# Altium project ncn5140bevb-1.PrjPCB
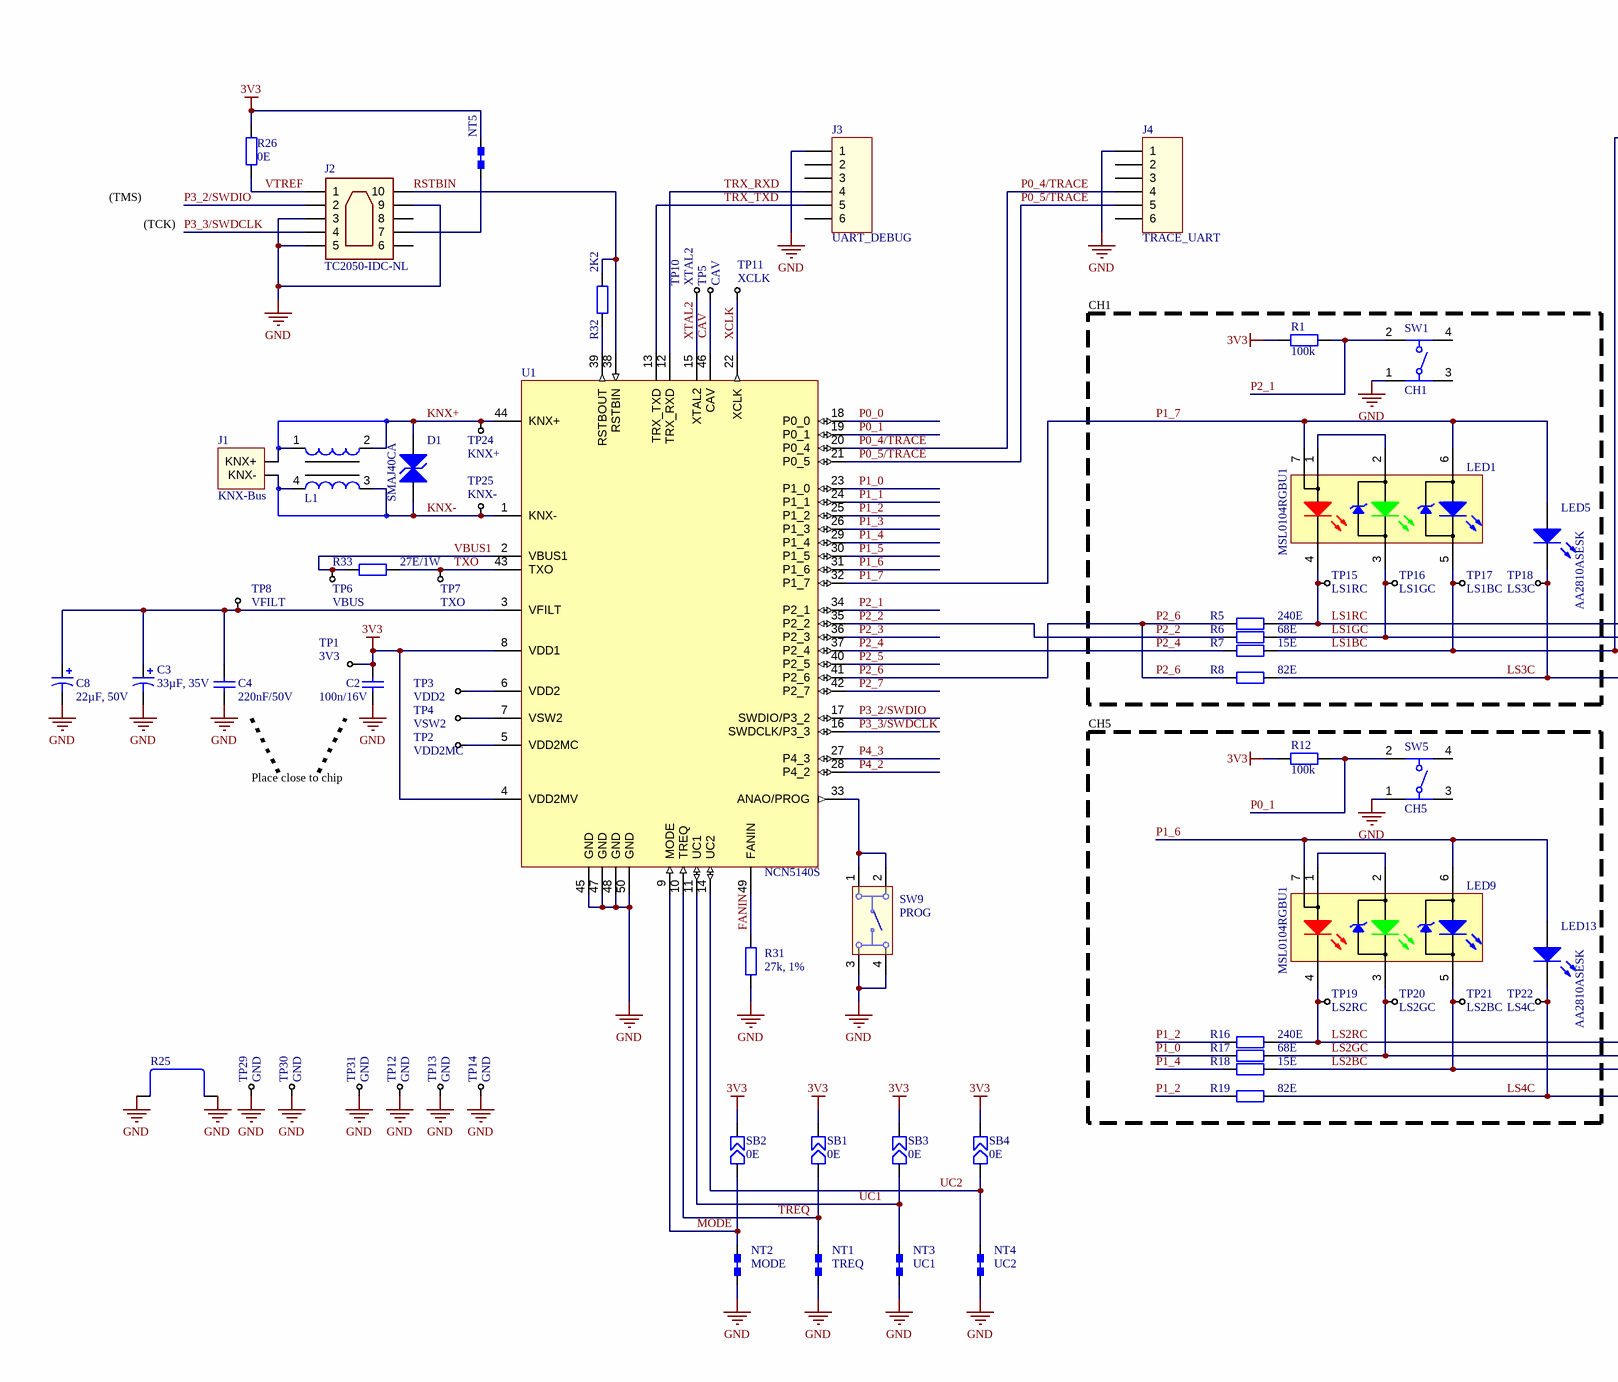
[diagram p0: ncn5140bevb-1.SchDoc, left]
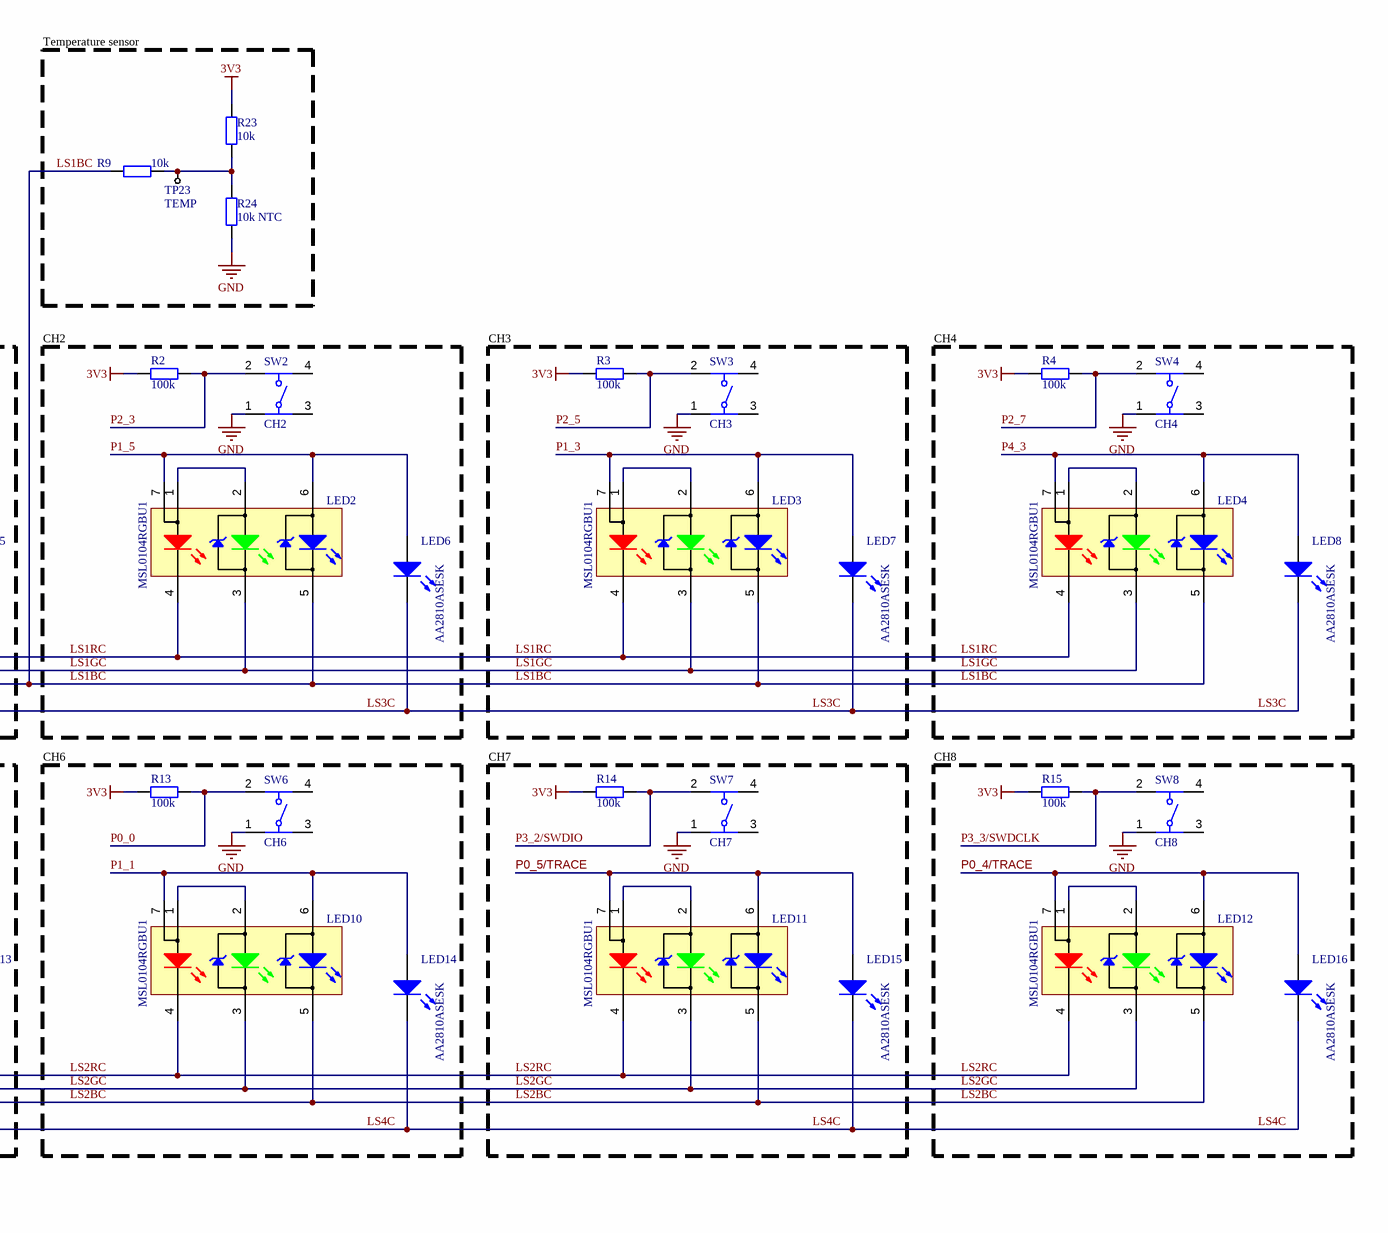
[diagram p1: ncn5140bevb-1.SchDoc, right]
ProjectBoardName: ncn5140bevb-1; ProjectEngineer: Tijl Schepens; ProjectOrganization: ON Semiconductor — Energy Management Products; ProjectRevision: -; ProjectTitle: NCN5140 EVB with tactile buttons
1 sheet, 96 parts. Net scope: global (net labels, ports and power ports of the same name join across sheets).
Board file: ncn5140bevb-1.PcbDoc

## Sheet ncn5140bevb-1.SchDoc
size A2; Engineer: Tijl Schepens; Organization: ON Semiconductor — Energy Management Products; Revision: -; SheetNumber: 1; SheetTotal: 1; BoardName: ncn5140bevb-1

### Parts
C2  value 100n/16V  [CAPC1608L]  (hidden comment: Cap)
C3  value 33µF, 35V  [T598]  (hidden comment: T598D336M035ATE065)
C4  value 220nF/50V  [CAPC1608L]  (hidden comment: Cap)
C8  value 22µF, 50V  [CAPPSMD-6.3x5.8_L]  (hidden comment: Cap)
D1  SMAJ40CA  [DIOM4326X23N]
J1  KNX-Bus  [EIB_BUS_COUPLER_2P_FULL_8.5]
J2  TC2050-IDC-NL  [TC2050-IDC-NL]
J3  Usage: UART_DEBUG  [61300611121]  (hidden comment: 61300611121)
J4  Usage: TRACE_UART  [61300611121]  (hidden comment: 61300611121)
L1  50475C  [5000_Series]  (value not drawn)  (net tie, no BOM)
LED1  MSL0104RGBU1  [MSL0104RGB]
LED2  MSL0104RGBU1  [MSL0104RGB]
LED3  MSL0104RGBU1  [MSL0104RGB]
LED4  MSL0104RGBU1  [MSL0104RGB]
LED5  AA2810ASESK  [AA2810A]
LED6  AA2810ASESK  [AA2810A]
LED7  AA2810ASESK  [AA2810A]
LED8  AA2810ASESK  [AA2810A]
LED9  MSL0104RGBU1  [MSL0104RGB]
LED10  MSL0104RGBU1  [MSL0104RGB]
LED11  MSL0104RGBU1  [MSL0104RGB]
LED12  MSL0104RGBU1  [MSL0104RGB]
LED13  AA2810ASESK  [AA2810A]
LED14  AA2810ASESK  [AA2810A]
LED15  AA2810ASESK  [AA2810A]
LED16  AA2810ASESK  [AA2810A]
NT1  TREQ  [NetTie-1005L]  (net tie, no BOM)
NT2  MODE  [NetTie-1005L]  (net tie, no BOM)
NT3  UC1  [NetTie-1005L]  (net tie, no BOM)
NT4  UC2  [NetTie-1005L]  (net tie, no BOM)
NT5  NetTie  [NetTie-1608L]  (value not drawn)  (net tie, no BOM)
R1  value 100k  [RESC1608L]
R2  value 100k  [RESC1608L]
R3  value 100k  [RESC1608L]
R4  value 100k  [RESC1608L]
R5  value 240E  [RESC1608L]
R6  value 68E  [RESC1608L]
R7  value 15E  [RESC1608L]
R8  value 82E  [RESC1608L]
R9  value 10k  [RESC1608L]
R12  value 100k  [RESC1608L]
R13  value 100k  [RESC1608L]
R14  value 100k  [RESC1608L]
R15  value 100k  [RESC1608L]
R16  value 240E  [RESC1608L]
R17  value 68E  [RESC1608L]
R18  value 15E  [RESC1608L]
R19  value 82E  [RESC1608L]
R23  value 10k  [RESC1608L]
R24  value 10k NTC  [RESC1608L]
R25  D3082-05  [Groundbar D3082-05]  (value not drawn)
R26  value 0E  [RESC1608L]
R31  value 27k, 1%  [RESC1608L]
R32  value 2K2  [RESC1608L]
R33  value 27E/1W  [RESC6332N]
SB1  value 0E  [1005-SB]  (hidden comment: TREQ)
SB2  value 0E  [1005-SB]  (hidden comment: MODE)
SB3  value 0E  [1005-SB]  (hidden comment: UC1)
SB4  value 0E  [1005-SB]  (hidden comment: UC2)
SW1  CH1  [430182070816]
SW2  CH2  [430182070816]
SW3  CH3  [430182070816]
SW4  CH4  [430182070816]
SW5  CH5  [430182070816]
SW6  CH6  [430182070816]
SW7  CH7  [430182070816]
SW8  CH8  [430182070816]
SW9  PROG  [430181038816]
TP1  3V3  [testpointpg-th]  (no BOM)
TP2  VDD2MC  [testpointpg-smt_N]  (no BOM)
TP3  VDD2  [testpointpg-smt_N]  (no BOM)
TP4  VSW2  [testpointpg-smt_N]  (no BOM)
TP5  CAV  [testpointpg-smt]  (no BOM)
TP6  VBUS  [testpointpg-th]  (no BOM)
TP7  TXO  [testpointpg-th]  (no BOM)
TP8  VFILT  [testpointpg-th]  (no BOM)
TP10  XTAL2  [testpointpg-smt_N]  (no BOM)
TP11  XCLK  [testpointpg-th]  (no BOM)
TP12  GND  [testpointpg-th]  (no BOM)
TP13  GND  [testpointpg-th]  (no BOM)
TP14  GND  [testpointpg-th]  (no BOM)
TP15  LS1RC  [testpointpg-th]  (no BOM)
TP16  LS1GC  [testpointpg-th]  (no BOM)
TP17  LS1BC  [testpointpg-th]  (no BOM)
TP18  LS3C  [testpointpg-th]  (no BOM)
TP19  LS2RC  [testpointpg-th]  (no BOM)
TP20  LS2GC  [testpointpg-th]  (no BOM)
TP21  LS2BC  [testpointpg-th]  (no BOM)
TP22  LS4C  [testpointpg-th]  (no BOM)
TP23  TEMP  [testpointpg-th]  (no BOM)
TP24  KNX+  [testpointpg-th]  (no BOM)
TP25  KNX-  [testpointpg-th]  (no BOM)
TP29  GND  [testpointpg-th]  (no BOM)
TP30  GND  [testpointpg-th]  (no BOM)
TP31  GND  [testpointpg-th]  (no BOM)
U1  NCN5140S  [127FD]

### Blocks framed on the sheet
Temperature sensor: R9 R23 R24 TP23
CH1: LED1 LED5 R1 R5-R8 SW1 TP15-TP18
CH2: LED2 LED6 R2 SW2
CH3: LED3 LED7 R3 SW3
CH4: LED4 LED8 R4 SW4
CH5: LED9 LED13 R12 R16-R19 SW5 TP19-TP22
CH6: LED10 LED14 R13 SW6
CH7: LED11 LED15 R14 SW7
CH8: LED12 LED16 R15 SW8

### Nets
3V3: C2.2 NT5.2 R1.2 R2.2 R3.2 R4.2 R12.2 R13.2 R14.2 R15.2 R23.2 R26.2 SB1.1 SB2.1 SB3.1 SB4.1 TP1.1 U1.4(VDD2MV) U1.8(VDD1)
GND: C2.1 C3.2 C4.1 C8.2 J2.3 J2.5 J2.9 J3.1 J4.1 NT1.1 NT2.1 NT3.1 NT4.1 R24.1 R25.1 R25.2 R31.2 SW1.1 SW2.1 SW3.1 SW4.1 SW5.1 SW6.1 SW7.1 SW8.1 SW9.3 SW9.4 TP12.1 TP13.1 TP14.1 TP29.1 TP30.1 TP31.1 U1.45(GND) U1.47(GND) U1.48(GND) U1.50(GND)
CAV: TP5.1 U1.46(CAV)
FANIN: R31.1 U1.49(FANIN)
KNX+: D1.2(K) L1.2 TP24.1 U1.44(KNX+)
KNX-: D1.1(A) L1.3 TP25.1 U1.1(KNX-)
LS1BC: LED1.5(KB) LED2.5(KB) LED3.5(KB) LED4.5(KB) R7.2 R9.2 TP17.1
LS1GC: LED1.3(KG) LED2.3(KG) LED3.3(KG) LED4.3(KG) R6.2 TP16.1
LS1RC: LED1.4(KR) LED2.4(KR) LED3.4(KR) LED4.4(KR) R5.2 TP15.1
LS2BC: LED9.5(KB) LED10.5(KB) LED11.5(KB) LED12.5(KB) R18.2 TP21.1
LS2GC: LED9.3(KG) LED10.3(KG) LED11.3(KG) LED12.3(KG) R17.2 TP20.1
LS2RC: LED9.4(KR) LED10.4(KR) LED11.4(KR) LED12.4(KR) R16.2 TP19.1
LS3C: LED5.2(K) LED6.2(K) LED7.2(K) LED8.2(K) R8.1 TP18.1
LS4C: LED13.2(K) LED14.2(K) LED15.2(K) LED16.2(K) R19.1 TP22.1
MODE: NT2.2 SB2.2 U1.9(MODE)
P0_0: R13.1 SW6.2 U1.18(P0_0)
P0_1: R12.1 SW5.2 U1.19(P0_1)
P0_4/TRACE: J4.4 LED12.6(AB) LED12.7(AR) LED16.1(A) U1.20(P0_4)
P0_5/TRACE: J4.5 LED11.6(AB) LED11.7(AR) LED15.1(A) U1.21(P0_5)
P1_0: R17.1 U1.23(P1_0)
P1_1: LED10.6(AB) LED10.7(AR) LED14.1(A) U1.24(P1_1)
P1_2: R16.1 R19.2 U1.25(P1_2)
P1_3: LED3.6(AB) LED3.7(AR) LED7.1(A) U1.26(P1_3)
P1_4: R18.1 U1.29(P1_4)
P1_5: LED2.6(AB) LED2.7(AR) LED6.1(A) U1.30(P1_5)
P1_6: LED9.6(AB) LED9.7(AR) LED13.1(A) U1.31(P1_6)
P1_7: LED1.6(AB) LED1.7(AR) LED5.1(A) U1.32(P1_7)
P2_1: R1.1 SW1.2 U1.34(P2_1)
P2_2: R6.1 U1.35(P2_2)
P2_3: R2.1 SW2.2 U1.36(P2_3)
P2_4: R7.1 U1.37(P2_4)
P2_5: R3.1 SW3.2 U1.40(P2_5)
P2_6: R5.1 R8.2 U1.41(P2_6)
P2_7: R4.1 SW4.2 U1.42(P2_7)
P3_2/SWDIO: J2.2 R14.1 SW7.2 U1.17(SWDIO/P3_2)
P3_3/SWDCLK: J2.4 R15.1 SW8.2 U1.16(SWDCLK/P3_3)
P4_2: U1.28(P4_2)
P4_3: LED4.6(AB) LED4.7(AR) LED8.1(A) U1.27(P4_3)
RSTBIN: J2.10 R32.2 U1.38(RSTBIN)
TREQ: NT1.2 SB1.2 U1.10(TREQ)
TRX_RXD: J3.4 U1.12(TRX_RXD)
TRX_TXD: J3.5 U1.13(TRX_TXD)
TXO: R33.1 TP7.1 U1.43(TXO)
UC1: NT3.2 SB3.2 U1.11(UC1)
UC2: NT4.2 SB4.2 U1.14(UC2)
VBUS1: R33.2 TP6.1 U1.2(VBUS1)
VTREF: J2.1 R26.1
XCLK: TP11.1 U1.22(XCLK)
XTAL2: TP10.1 U1.15(XTAL2)
NetC3_1: C3.1 C4.2 C8.1 TP8.1 U1.3(VFILT)
NetJ1_1: J1.1(KNX-) L1.4
NetJ1_2: J1.2(KNX+) L1.1
NetJ2_7: J2.7 NT5.1
NetLED1_1: LED1.1(AR) LED1.2(AG)
NetLED2_1: LED2.1(AR) LED2.2(AG)
NetLED3_1: LED3.1(AR) LED3.2(AG)
NetLED4_1: LED4.1(AR) LED4.2(AG)
NetLED9_1: LED9.1(AR) LED9.2(AG)
NetLED10_1: LED10.1(AR) LED10.2(AG)
NetLED11_1: LED11.1(AR) LED11.2(AG)
NetLED12_1: LED12.1(AR) LED12.2(AG)
NetR9_1: R9.1 R23.1 R24.2 TP23.1
NetR32_1: R32.1 U1.39(RSTBOUT)
NetSW9_1: SW9.1 SW9.2 U1.33(ANAO/PROG)
NetTP2_1: TP2.1 U1.5(VDD2MC)
NetTP3_1: TP3.1 U1.6(VDD2)
NetTP4_1: TP4.1 U1.7(VSW2)

Not connected (* = marked no-connect by the designer): J2 6 8; J3 2 3 6; J4 2 3 6; SW1 3 4; SW2 3 4; SW3 3 4; SW4 3 4; SW5 3 4; SW6 3 4; SW7 3 4; SW8 3 4

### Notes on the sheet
- (TMS)
- (TCK)
- Place close to chip

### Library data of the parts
C2 = Cap: Capacitor; PartNumber: GCM188R71C104KA37D
C3 = T598D336M035ATE065: T598, Tantalum, Polymer Tantalum, 33 uF, 20%, 35 VDC, SMD, Polymer, Molded, Low ESR, AEC-Q200, 65 mOhms, 7343, HeightMax = 3.1mm; Manufacturer: Kemet
C4 = Cap: Capacitor; Manufacturer: TDK Corporation; PartNumber: C1608X7R1H224K080AB
C8 = CapPol: Capacitor
D1 = SMAJ40CA: SMAJ40CA -  TVS Diode, TRANSZORB SMAJ Series, Bidirectional, 40 V, 64.5 V, DO-214AC, 2 Pins; Value: 40V, 400W
J1 = 243-211Male: Male connector for WAGO 243-211; Part_Number: 2 x 13.14.125; Manufacturer: Ettinger; Remarks: 2 pins needed, Farnell code is pack of 100; ID: 103; Pitch: 5,75mm; Pb-Free: Yes; Component Footprint: 5,75mm pitch; Pin_Count: 2; Rows: 1; Value: Pitch: 5,75mm/diameter: 1mm/100V/6A
J2 = TC2050-IDC-NL: TC2050-IDC-NL  10-Pin Plug-of-NailsTM Cable with Ribbon Connector; Manufacturer: Tag-Connect
J3 J4 = 61300611121: WR-PHD 2.54 mm THT Pin Header, 6p; Pin Number: 6; Rated Current: 3 A; Working Voltage: 250 VAC; Withstanding Voltage: 500 VAC; Pitch: 2.54 mm
L1 = 50475C: surface-mount common mode choke; Manufacturer: Murata; Value: 4.7mH; 400mA
LED1-LED4 LED9-LED12 = MSL0104RGBU1: Side View LED, RGB, 6.9X2.2 mm, SMD, Rectangular, R 20mA, G 20mA, B 20mA; Manufacturer: Rohm Semiconductor
LED5-LED8 LED13-LED16 = AA2810ASESK: Red 625nm LED Indication - Discrete 2.2V 2-SMD, J-Lead; Manufacturer: Kingbright
NT1-NT4 = NetTie
R1-R4 R12-R15 = Res: Resistor; PartNumber: RC0603FR-07100KL
R5 R16 = Res: Resistor; PartNumber: MCWR06X2400FTL
R6 R17 = Res: Resistor; PartNumber: MCWR06X68R0FTL
R7 R18 = Res: Resistor; PartNumber: ASC0603-15RFT5
R8 R19 = Res: Resistor; PartNumber: CRGCQ0603F82R
R9 R23 = Res: Resistor; PartNumber: RC0603FR-0710KL
R24 = Res: Resistor; PartNumber: ERT-J1VG103FA
R25 = D3082-05: 2 (1 x 2) Position Shunt Connector Non-Insulated 0.400" (10.16mm) Gold; Manufacturer: Harwin; Value: 2 pins
R26 = Res: Resistor; PartNumber: RC0603JR-070RL
R31 = Res: Resistor; PartNumber: CR0603-FX-2702ELF
R32 = Res: Resistor; PartNumber: RC0603FR-072K2L
R33 = Res: Resistor; PartNumber: 352027RJT; Manufacturer: TE Connectivity
SB1-SB4 = SolderBridge: Solder bridge
SW1-SW8 = 430182070816: WS-TASV SMT Tact Switch 6x6mm, height 7mm, 160gf; Manufacturer: Wurth Elektronik; Rated Voltage: 12VDC; Rated Current: 50mA; Washable: No
SW9 = CMP-1454-00001-1: WS-TASV SMD Tact Switch 4.5X4.5 mm; Manufacturer: Wuerth Elektronik; NoPins: 04
TP1-TP8 TP10-TP25 TP29-TP31 = testpoint
U1 = NCN5140S: KNX System-in-Package (SiP); Manufacturer: ON Semiconductor

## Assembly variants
8button-RGB-Tantal: not fitted C8 D1 J2 L1 LED5 LED6 LED7 LED8 LED13 LED14 LED15 LED16 R8 R19 SB1 SB2 SB3 SB4
8button-RGB-Tantal-ND: not fitted C8 D1 J2 J3 J4 L1 LED5 LED6 LED7 LED8 LED13 LED14 LED15 LED16 R8 R19 R25 SB1 SB2 SB3 SB4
